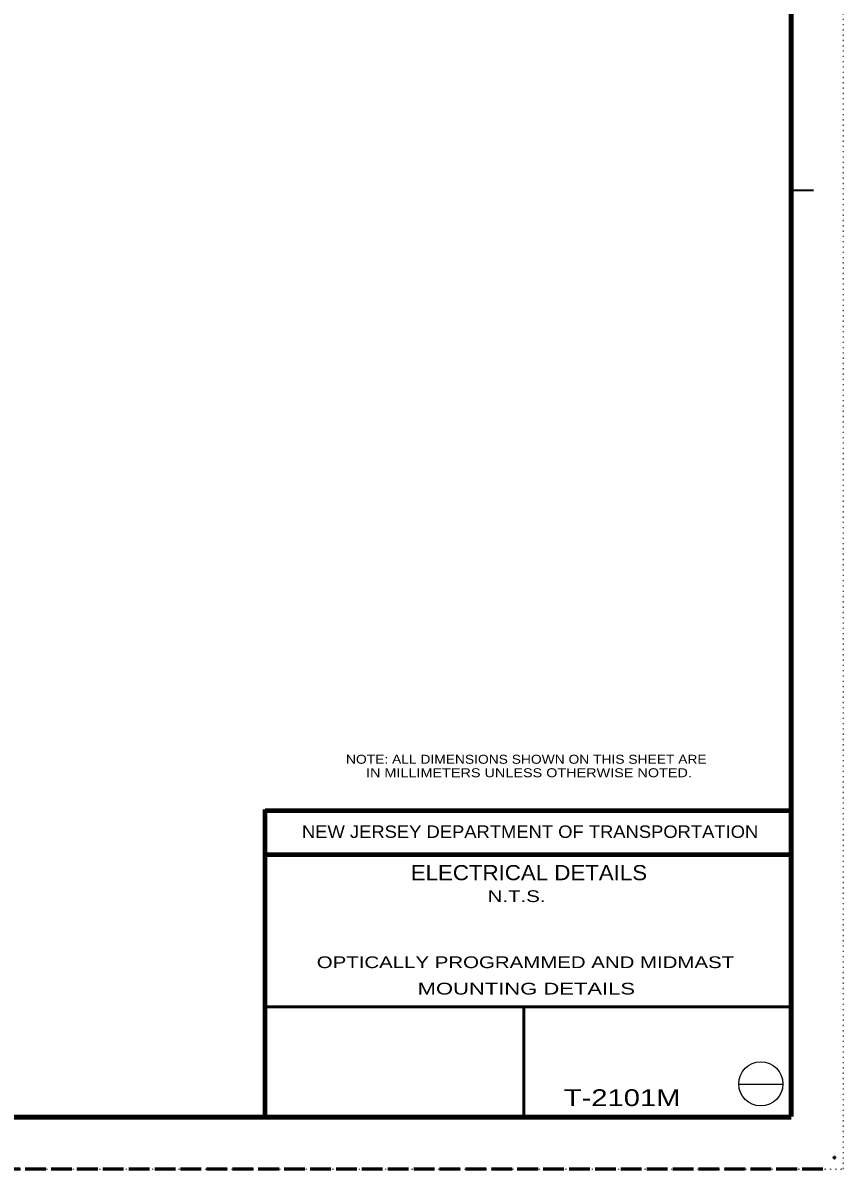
# Model space of a CAD drawing. Extents: x 312583 to 312854, y 144419 to 144597.
# Drawn here: x 312782.3 to 312853.5, y 144418.6 to 144518.1 of the extents above; entities that cross this region are included whole.
import ezdxf
from ezdxf.enums import TextEntityAlignment as Align

# ---------------------------------------------------------------- set-up
doc = ezdxf.new("R2010")
doc.units = 0
doc.header["$LTSCALE"] = 0.3
doc.header["$PDMODE"] = 32
doc.header["$PDSIZE"] = 0.15
doc.linetypes.add('DOTTED', pattern=[1.5, 0.3, -1.2])
doc.linetypes.add('LONG_DASHED', pattern=[7.5, 6, -1.5])
for name, color, linetype, lineweight in [('1', 7, 'Continuous', 40), ('10', 7, 'Continuous', 25), ('2', 7, 'Continuous', 40), ('62', 7, 'DOTTED', 13), ('63', 7, 'LONG_DASHED', 60)]:
    doc.layers.add(name, color=color, linetype=linetype, lineweight=lineweight)
doc.layers.add('5', color=7, linetype='Continuous')

msp = doc.modelspace()

# ---------------------------------------------------------------- linework, layer by layer
at = {"layer": '1', "lineweight": 158}
for p, q in [((312849, 144423.1446), (312849, 144585.0846)), ((312616.5, 144423.0846), (312849, 144423.0846))]:
    msp.add_line(p, q, dxfattribs=at)
at = {"layer": '1', "lineweight": 106}
msp.add_line((312849, 144423.1446), (312849, 144584.0756), dxfattribs=at)
at = {"layer": '1', "lineweight": 35}
msp.add_line((312849, 144503.6216), (312850.932, 144503.6216), dxfattribs=at)
at = {"layer": '1', "lineweight": 80}
for p, q in [((312803.31, 144423.1446), (312803.31, 144449.8146)), ((312803.31, 144449.7246), (312849, 144449.7246)), ((312803.31, 144445.9146), (312849, 144445.9146))]:
    msp.add_line(p, q, dxfattribs=at)
at = {"layer": '1', "lineweight": 53}
for p, q in [((312849, 144432.6666), (312803.31, 144432.6666)), ((312825.7547, 144432.6666), (312825.7547, 144423.1446))]:
    msp.add_line(p, q, dxfattribs=at)
at = {"layer": '1'}
msp.add_point((312852.75, 144419.5846), dxfattribs=at)
at = {"layer": '10'}
msp.add_line((312844.4383, 144425.966), (312848.2793, 144425.966), dxfattribs=at)
msp.add_circle((312846.3494, 144425.9805), 1.9159, dxfattribs=at)
at = {"layer": '62'}
msp.add_lwpolyline([(312601.2, 144418.5846), (312853.5, 144418.5846), (312853.5, 144596.7846)], dxfattribs=at)
at = {"layer": '63'}
msp.add_line((312851.75, 144418.5846), (312583.526, 144418.5846), dxfattribs=at)

# ---------------------------------------------------------------- texts
at = {"layer": '1'}
for s, width, p in [('NOTE: ALL DIMENSIONS SHOWN ON THIS SHEET ARE', 1.15, (312810.321, 144453.7897)), ('     IN MILLIMETERS UNLESS OTHERWISE NOTED.', 1.2, (312810.3209, 144452.6197))]:
    msp.add_text(s, height=0.78, dxfattribs=dict(at, width=width)).set_placement(p)
at = {"layer": '1', "width": 1.1}
msp.add_text('ELECTRICAL DETAILS', height=1.315, dxfattribs=at).set_placement((312826.2109, 144443.676), align=Align.CENTER)
at = {"layer": '10', "width": 1.1}
msp.add_text('NEW JERSEY DEPARTMENT OF TRANSPORTATION', height=1.085, dxfattribs=at).set_placement((312826.3118, 144447.3492), align=Align.CENTER)
at = {"layer": '2'}
for s, width, p in [('    N.T.S.  ', 1.3, (312824.6461, 144441.778)), ('      OPTICALLY PROGRAMMED AND MIDMAST      ', 1.3, (312825.908, 144436.04)), ('              MOUNTING DETAILS              ', 1.4, (312825.9846, 144433.7476))]:
    msp.add_text(s, height=1.02, dxfattribs=dict(at, width=width)).set_placement(p, align=Align.CENTER)
at = {"layer": '5', "width": 1.3}
msp.add_text('T-2101M   ', height=1.457, dxfattribs=at).set_placement((312835.3614, 144424.057), align=Align.CENTER)

doc.saveas('drawing.dxf')
